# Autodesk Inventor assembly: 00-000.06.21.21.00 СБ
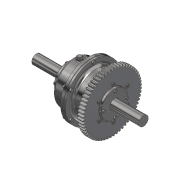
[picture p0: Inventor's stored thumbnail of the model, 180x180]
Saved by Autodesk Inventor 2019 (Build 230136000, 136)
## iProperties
Created: 2019-01
Part Number: 00-000.06.21.21.00 СБ
Document SubType Name: Assembly
Designer: m.vorobev
Author: m.vorobev
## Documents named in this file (31)
- C:\Users\m.vorobev.TRINITY\Documents\Inventor\00-000.06.21.21.00\00-000.06.21.21.00 СБ.iam
- C:\Users\m.vorobev.TRINITY\Documents\Inventor\00-000.06.21.21.00\00-000.06.21.21.10.ipt
- C:\Users\m.vorobev.TRINITY\Documents\Inventor\00-000.06.21.21.00\00-000.06.21.21.01.ipt
- C:\Users\m.vorobev.TRINITY\Documents\Inventor\00-000.06.21.21.00\00-000.06.21.21.02.ipt
- C:\Users\m.vorobev.TRINITY\Documents\Inventor\00-000.06.21.21.00\Content Center Files\en-US\Bolt GOST 7798-78\Bolt  M10-6g×35(S16) GOST 7798-70.ipt
- C:\Users\m.vorobev.TRINITY\Documents\Inventor\00-000.06.21.21.00\Content Center Files\en-US\GOST 6402-70\Washer  10 L GOST 6402-70.ipt
- C:\Users\m.vorobev.TRINITY\Documents\Inventor\00-000.06.21.21.00\Content Center Files\en-US\GOST 5916-70\Nut M10-6H GOST 5916-70.ipt
- C:\Users\m.vorobev.TRINITY\Documents\Inventor\00-000.06.21.21.00\00-000.06.21.21.15.ipt
- C:\Users\m.vorobev.TRINITY\Documents\Inventor\00-000.06.21.21.00\00-000.06.21.21.05.ipt
- C:\Users\m.vorobev.TRINITY\Documents\Inventor\00-000.06.21.21.00\Key 2-36x20x100 GOST 23360-78.ipt
- C:\Users\m.vorobev.TRINITY\Documents\Inventor\00-000.06.21.21.00\Content Center Files\en-US\Stud GOST 22034-76\Stud M10-6g×45 GOST 22034-76.ipt
- C:\Users\m.vorobev.TRINITY\Documents\Inventor\00-000.06.21.21.00\00-000.06.21.21.07.ipt
- C:\Users\m.vorobev.TRINITY\Documents\Inventor\00-000.06.21.21.00\00-000.06.21.21.11,12,13\00-000.06.21.21.12.ipt
- C:\Users\m.vorobev.TRINITY\Documents\Inventor\00-000.06.21.21.00\00-000.06.21.21.11,12,13.ipt
- C:\Users\m.vorobev.TRINITY\Documents\Inventor\00-000.06.21.21.00\00-000.06.21.21.03.ipt
- C:\Users\m.vorobev.TRINITY\Documents\Inventor\00-000.06.21.21.00\00-000.06.21.21.04.ipt
- C:\Users\m.vorobev.TRINITY\Documents\Inventor\00-000.06.21.21.00\Key 2-12x8x28 GOST 23360-78.ipt
- C:\Users\m.vorobev.TRINITY\Documents\Inventor\00-000.06.21.21.00\Content Center Files\en-US\Nut GOST 12460-67\Nut 7003-0141 GOST 12460-67.ipt
- C:\Users\m.vorobev.TRINITY\Documents\Inventor\00-000.06.21.21.00\00-000.06.21.21.11,12,13\00-000.06.21.21.11.ipt
- C:\Users\m.vorobev.TRINITY\Documents\Inventor\00-000.06.21.21.00\Content Center Files\en-US\GOST 8338-75\Bearing 309 GOST 8338-75.ipt
- C:\Users\m.vorobev.TRINITY\Documents\Inventor\00-000.06.21.21.00\00-000.06.21.21.11,12,13\00-000.06.21.21.13.ipt
- C:\Users\m.vorobev.TRINITY\Documents\Inventor\00-000.06.21.21.00\00-000.06.21.21.08,09\00-000.06.21.21.08.ipt
- C:\Users\m.vorobev.TRINITY\Documents\Inventor\00-000.06.21.21.00\00-000.06.21.21.08,09.ipt
- C:\Users\m.vorobev.TRINITY\Documents\Inventor\00-000.06.21.21.00\00-000.06.21.21.08,09\00-000.06.21.21.09.ipt
- C:\Users\m.vorobev.TRINITY\Documents\Inventor\00-000.06.21.21.00\00-000.06.21.21.29.ipt
- C:\Users\m.vorobev.TRINITY\Documents\Inventor\00-000.06.21.21.00\Content Center Files\en-US\GOST 6402-70\Washer  8 L GOST 6402-70.ipt
- C:\Users\m.vorobev.TRINITY\Documents\Inventor\00-000.06.21.21.00\Content Center Files\en-US\Bolt GOST 7798-78\Bolt  M8-6g×35(S13) GOST 7798-70.ipt
- C:\Users\m.vorobev.TRINITY\Documents\Inventor\00-000.06.21.21.00\00-000.06.21.21.06.ipt
- C:\Users\m.vorobev.TRINITY\Documents\Inventor\00-000.06.21.21.00\00-000.06.21.21.17.ipt
- C:\Users\m.vorobev.TRINITY\Documents\Inventor\00-000.06.21.21.00\00-000.06.21.21.16.ipt
- C:\Users\m.vorobev.TRINITY\Documents\Inventor\00-000.06.21.21.00\00-000.06.21.21.14.ipt
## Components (106 placed, 28 different names)
1. 00-000.06.21.21.05:1 — Angle:1, Insert:21, Flush:1, Angle:4, Mate:25
2. 00-000.06.21.21.10:1 — Mate:4, Mate:5, Mate:6, Mate:7, Mate:8, Mate:16, Mate:23
3. 00-000.06.21.21.01:1 — Mate:19, Insert:70, Mate:21, Insert:90, Mate:22, Insert:93, Insert:95, Insert:97, Mate:24, Mate:26
4. 00-000.06.21.21.02:1 — Insert:19, Mate:1, Mate:2, Mate:3, Insert:20, Insert:21, Mate:18, Insert:53, Insert:71, Mate:20, Mate:23, Insert:95
5. 00-000.06.21.21.15:1 — Insert:19
6. Key 2-36x20x100 GOST 23360-78:1 — Mate:1, Mate:2, Mate:3, Angle:1
7. 00-000.06.21.21.07:1 — Mate:14, Insert:44, Mate:15, Mate:17, Insert:45, Insert:46, Insert:47, Insert:48, Mate:24
8. 00-000.06.21.21.12:1 — Insert:38, Insert:44
9. 00-000.06.21.21.12:2 — Insert:39, Insert:47
10. 00-000.06.21.21.12:3 — Insert:41, Insert:46
11. 00-000.06.21.21.12:4 — Insert:40, Insert:45
12. 00-000.06.21.21.03:1 — Insert:38, Rotation:3
13. 00-000.06.21.21.03:2 — Insert:39, Rotation:2
14. 00-000.06.21.21.03:3 — Insert:40, Rotation:4
15. 00-000.06.21.21.03:4 — Insert:41, Rotation:2, Rotation:3, Rotation:4, Rotation:5
16. 00-000.06.21.21.04:1 — Mate:7, Angle:2, Mate:8, Insert:42, Mate:15, Insert:49, Rotation:1, Rotation:5, Rotating
17. Key 2-12x8x28 GOST 23360-78:1 — Mate:4, Mate:5, Mate:6, Angle:2
18. 00-000.06.21.21.10:2 — Mate:16, Mate:22
19. 00-000.06.21.21.04:2 — Mate:17, Insert:50, Rotation:1
20. Key 2-12x8x28 GOST 23360-78:2
21. 00-000.06.21.21.11:5 — Insert:48
22. 00-000.06.21.21.13:6 — Insert:49
23. 00-000.06.21.21.13:7 — Insert:50
24. 00-000.06.21.21.08:1 — Insert:51, Mate:18, Insert:53, Insert:80
25. 00-000.06.21.21.09:2 — Insert:52, Insert:63, Insert:67, Insert:68, Insert:69, Mate:19, Insert:70, Insert:89, Insert:91
26. 00-000.06.21.21.29:1 — Insert:51
27. 00-000.06.21.21.29:2 — Insert:52
28. 00-000.06.21.21.06:1 — Insert:71, Mate:20, Insert:76, Insert:77, Insert:78, Insert:79
29. 00-000.06.21.21.06:2 — Mate:21, Insert:90
30. 00-000.06.21.21.17:1 — Insert:93, Insert:94
31. 00-000.06.21.21.16:1 — Insert:91
32. 00-000.06.21.21.14:1 — Insert:94
33. 00-000.06.21.21.17:2 — Insert:97
34. 00-000.06.21.21.14:2
35. Bolt GOST 7798-70 M10-6g×35(S16):1
36. Bolt GOST 7798-70 M10-6g×35(S16):2
37. Bolt GOST 7798-70 M10-6g×35(S16):3
38. Bolt GOST 7798-70 M10-6g×35(S16):4
39. Bolt GOST 7798-70 M10-6g×35(S16):5
40. Bolt GOST 7798-70 M10-6g×35(S16):6
41. Washer GOST 6402-70 10 L:1
42. Washer GOST 6402-70 10 L:2
43. Washer GOST 6402-70 10 L:3
44. Washer GOST 6402-70 10 L:4
45. Washer GOST 6402-70 10 L:5
46. Washer GOST 6402-70 10 L:6
47. Nut GOST 5916-70 M10:1
48. Nut GOST 5916-70 M10:2
49. Nut GOST 5916-70 M10:3
50. Nut GOST 5916-70 M10:4
51. Nut GOST 5916-70 M10:5
52. Nut GOST 5916-70 M10:6
53. Washer GOST 6402-70 10 L:7 — Insert:28
54. Washer GOST 6402-70 10 L:8 — Insert:33
55. Washer GOST 6402-70 10 L:9 — Insert:32
56. Washer GOST 6402-70 10 L:10 — Insert:31
57. Washer GOST 6402-70 10 L:11 — Insert:30
58. Washer GOST 6402-70 10 L:12 — Insert:29
59. Nut GOST 5916-70 M10:7 — Insert:28
60. Nut GOST 5916-70 M10:8 — Insert:33
61. Nut GOST 5916-70 M10:9 — Insert:29
62. Nut GOST 5916-70 M10:10 — Insert:30
63. Nut GOST 5916-70 M10:11 — Insert:31
64. Nut GOST 5916-70 M10:12 — Insert:32
65. Nut GOST 12460-67 7003-0141:1 — Insert:42, Mate:14
66. Nut GOST 12460-67 7003-0141:3
67. Bearing GOST 8338-75 309:1 — Insert:89
68. Washer GOST 6402-70 8 L:1
69. Washer GOST 6402-70 8 L:2 — Insert:59
70. Washer GOST 6402-70 8 L:3 — Insert:61
71. Washer GOST 6402-70 8 L:4 — Insert:60
72. Bolt GOST 7798-70 M8-6g×35(S13):1
73. Bolt GOST 7798-70 M8-6g×35(S13):2 — Insert:59
74. Bolt GOST 7798-70 M8-6g×35(S13):3 — Insert:61
75. Bolt GOST 7798-70 M8-6g×35(S13):4 — Insert:60
76. Washer GOST 6402-70 8 L:5 — Insert:63
77. Bolt GOST 7798-70 M8-6g×35(S13):5
78. Washer GOST 6402-70 8 L:6 — Insert:68
79. Bolt GOST 7798-70 M8-6g×35(S13):6
80. Washer GOST 6402-70 8 L:7 — Insert:69
81. Bolt GOST 7798-70 M8-6g×35(S13):7
82. Washer GOST 6402-70 8 L:8 — Insert:67
83. Bolt GOST 7798-70 M8-6g×35(S13):8
84. Washer GOST 6402-70 8 L:9 — Insert:78
85. Bolt GOST 7798-70 M8-6g×35(S13):9
86. Washer GOST 6402-70 8 L:10 — Insert:76
87. Bolt GOST 7798-70 M8-6g×35(S13):10
88. Washer GOST 6402-70 8 L:11 — Insert:79
89. Bolt GOST 7798-70 M8-6g×35(S13):11
90. Washer GOST 6402-70 8 L:12 — Insert:77
91. Bolt GOST 7798-70 M8-6g×35(S13):12
92. Bearing GOST 8338-75 309:2 — Insert:80
93. Washer GOST 6402-70 8 L:13
94. Bolt GOST 7798-70 M8-6g×35(S13):13
95. Washer GOST 6402-70 8 L:14
96. Bolt GOST 7798-70 M8-6g×35(S13):14
97. Washer GOST 6402-70 8 L:15
98. Bolt GOST 7798-70 M8-6g×35(S13):15
99. Washer GOST 6402-70 8 L:16
100. Bolt GOST 7798-70 M8-6g×35(S13):16
101. Stud GOST 22034-76 M10-6g×45:1 — Insert:20
102. Stud GOST 22034-76 M10-6g×45:2
103. Stud GOST 22034-76 M10-6g×45:3
104. Stud GOST 22034-76 M10-6g×45:4
105. Stud GOST 22034-76 M10-6g×45:5
106. Stud GOST 22034-76 M10-6g×45:6
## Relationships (76: Insert 45, Mate 21, RelateRotation 5, Angle 4, Flush 1)
- Insert:19: 00-000.06.21.21.02:1 ↔ 00-000.06.21.21.15:1
- Mate:1: 00-000.06.21.21.02:1 ↔ Key 2-36x20x100 GOST 23360-78:1
- Mate:2: 00-000.06.21.21.02:1 ↔ Key 2-36x20x100 GOST 23360-78:1
- Mate:3: 00-000.06.21.21.02:1 ↔ Key 2-36x20x100 GOST 23360-78:1
- Insert:20: 00-000.06.21.21.02:1 ↔ Stud GOST 22034-76 M10-6g×45:1
- Angle:1: 00-000.06.21.21.05:1 ↔ Key 2-36x20x100 GOST 23360-78:1
- Insert:21: 00-000.06.21.21.05:1 ↔ 00-000.06.21.21.02:1
- Insert:28: Washer GOST 6402-70 10 L:7 ↔ Nut GOST 5916-70 M10:7
- Insert:29: Washer GOST 6402-70 10 L:12 ↔ Nut GOST 5916-70 M10:9
- Insert:30: Washer GOST 6402-70 10 L:11 ↔ Nut GOST 5916-70 M10:10
- Insert:31: Washer GOST 6402-70 10 L:10 ↔ Nut GOST 5916-70 M10:11
- Insert:32: Washer GOST 6402-70 10 L:9 ↔ Nut GOST 5916-70 M10:12
- Insert:33: Washer GOST 6402-70 10 L:8 ↔ Nut GOST 5916-70 M10:8
- Insert:38: 00-000.06.21.21.12:1 ↔ 00-000.06.21.21.03:1
- Insert:39: 00-000.06.21.21.12:2 ↔ 00-000.06.21.21.03:2
- Insert:40: 00-000.06.21.21.12:4 ↔ 00-000.06.21.21.03:3
- Insert:41: 00-000.06.21.21.12:3 ↔ 00-000.06.21.21.03:4
- Mate:4: 00-000.06.21.21.10:1 ↔ Key 2-12x8x28 GOST 23360-78:1
- Mate:5: 00-000.06.21.21.10:1 ↔ Key 2-12x8x28 GOST 23360-78:1
- Mate:6: 00-000.06.21.21.10:1 ↔ Key 2-12x8x28 GOST 23360-78:1
- Mate:7: 00-000.06.21.21.10:1 ↔ 00-000.06.21.21.04:1
- Angle:2: 00-000.06.21.21.04:1 ↔ Key 2-12x8x28 GOST 23360-78:1
- Mate:8: 00-000.06.21.21.10:1 ↔ 00-000.06.21.21.04:1
- Insert:42: 00-000.06.21.21.04:1 ↔ Nut GOST 12460-67 7003-0141:1
- Mate:14: 00-000.06.21.21.07:1 ↔ Nut GOST 12460-67 7003-0141:1
- Insert:44: 00-000.06.21.21.07:1 ↔ 00-000.06.21.21.12:1
- Mate:15: 00-000.06.21.21.07:1 ↔ 00-000.06.21.21.04:1
- Mate:16: 00-000.06.21.21.10:1 ↔ 00-000.06.21.21.10:2
- Mate:17: 00-000.06.21.21.07:1 ↔ 00-000.06.21.21.04:2
- Insert:45: 00-000.06.21.21.07:1 ↔ 00-000.06.21.21.12:4
- Insert:46: 00-000.06.21.21.07:1 ↔ 00-000.06.21.21.12:3
- Insert:47: 00-000.06.21.21.07:1 ↔ 00-000.06.21.21.12:2
- Insert:48: 00-000.06.21.21.07:1 ↔ 00-000.06.21.21.11:5
- Insert:49: 00-000.06.21.21.04:1 ↔ 00-000.06.21.21.13:6
- Insert:50: 00-000.06.21.21.04:2 ↔ 00-000.06.21.21.13:7
- Insert:51: 00-000.06.21.21.08:1 ↔ 00-000.06.21.21.29:1
- Insert:52: 00-000.06.21.21.09:2 ↔ 00-000.06.21.21.29:2
- Mate:18: 00-000.06.21.21.02:1 ↔ 00-000.06.21.21.08:1
- Insert:53: 00-000.06.21.21.02:1 ↔ 00-000.06.21.21.08:1
- Insert:59: Washer GOST 6402-70 8 L:2 ↔ Bolt GOST 7798-70 M8-6g×35(S13):2
- Insert:60: Washer GOST 6402-70 8 L:4 ↔ Bolt GOST 7798-70 M8-6g×35(S13):4
- Insert:61: Washer GOST 6402-70 8 L:3 ↔ Bolt GOST 7798-70 M8-6g×35(S13):3
- Insert:63: 00-000.06.21.21.09:2 ↔ Washer GOST 6402-70 8 L:5
- Insert:67: 00-000.06.21.21.09:2 ↔ Washer GOST 6402-70 8 L:8
- Insert:68: 00-000.06.21.21.09:2 ↔ Washer GOST 6402-70 8 L:6
- Insert:69: 00-000.06.21.21.09:2 ↔ Washer GOST 6402-70 8 L:7
- Mate:19: 00-000.06.21.21.01:1 ↔ 00-000.06.21.21.09:2
- Insert:70: 00-000.06.21.21.01:1 ↔ 00-000.06.21.21.09:2
- Insert:71: 00-000.06.21.21.02:1 ↔ 00-000.06.21.21.06:1
- Mate:20: 00-000.06.21.21.02:1 ↔ 00-000.06.21.21.06:1
- Insert:76: 00-000.06.21.21.06:1 ↔ Washer GOST 6402-70 8 L:10
- Insert:77: 00-000.06.21.21.06:1 ↔ Washer GOST 6402-70 8 L:12
- Insert:78: 00-000.06.21.21.06:1 ↔ Washer GOST 6402-70 8 L:9
- Insert:79: 00-000.06.21.21.06:1 ↔ Washer GOST 6402-70 8 L:11
- Insert:80: 00-000.06.21.21.08:1 ↔ Bearing GOST 8338-75 309:2
- Mate:21: 00-000.06.21.21.01:1 ↔ 00-000.06.21.21.06:2
- Insert:89: 00-000.06.21.21.09:2 ↔ Bearing GOST 8338-75 309:1
- Insert:90: 00-000.06.21.21.01:1 ↔ 00-000.06.21.21.06:2
- Mate:22: 00-000.06.21.21.01:1 ↔ 00-000.06.21.21.10:2
- Mate:23: 00-000.06.21.21.10:1 ↔ 00-000.06.21.21.02:1
- Insert:91: 00-000.06.21.21.09:2 ↔ 00-000.06.21.21.16:1
- Insert:93: 00-000.06.21.21.01:1 ↔ 00-000.06.21.21.17:1
- Insert:94: 00-000.06.21.21.17:1 ↔ 00-000.06.21.21.14:1
- Insert:95: 00-000.06.21.21.01:1 ↔ 00-000.06.21.21.02:1
- Flush:1: 00-000.06.21.21.05:1
- Angle:4: 00-000.06.21.21.05:1
- Insert:97: 00-000.06.21.21.01:1 ↔ 00-000.06.21.21.17:2
- Mate:24: 00-000.06.21.21.01:1 ↔ 00-000.06.21.21.07:1
- Mate:25: 00-000.06.21.21.05:1
- Rotation:1 [RelateRotation]: 00-000.06.21.21.04:1 ↔ 00-000.06.21.21.04:2
- Rotation:2 [RelateRotation]: 00-000.06.21.21.03:2 ↔ 00-000.06.21.21.03:4
- Rotation:3 [RelateRotation]: 00-000.06.21.21.03:1 ↔ 00-000.06.21.21.03:4
- Rotation:4 [RelateRotation]: 00-000.06.21.21.03:3 ↔ 00-000.06.21.21.03:4
- Rotation:5 [RelateRotation]: 00-000.06.21.21.03:4 ↔ 00-000.06.21.21.04:1
- Rotating [Angle]: 00-000.06.21.21.04:1
- Mate:26: 00-000.06.21.21.01:1
## Named parameters: d52_d49 = 0, d54_d51 = 0, d55_d45 = 0, d56_d46 = 0, d57_d47 = 0, d58_d48 = 0, d88_d84 = 0, d90_d88_d84 = 0, d91_d88_d84 = 0, d92_d88_d84 = 0, d100_d84 = 0, d101_d100_d84 = 0, d102_d100_d84 = 0, d103_d100_d84 = 0, d109_d100_d84 = 0, d110_d101_d100_d84 = 0, d111_d102_d100_d84 = 0, d112_d103_d100_d84 = 0, d113_d104 = 0, d114_d105 = 0, d115_d106 = 0, d116_d107 = 0, d139_d125 = 0
